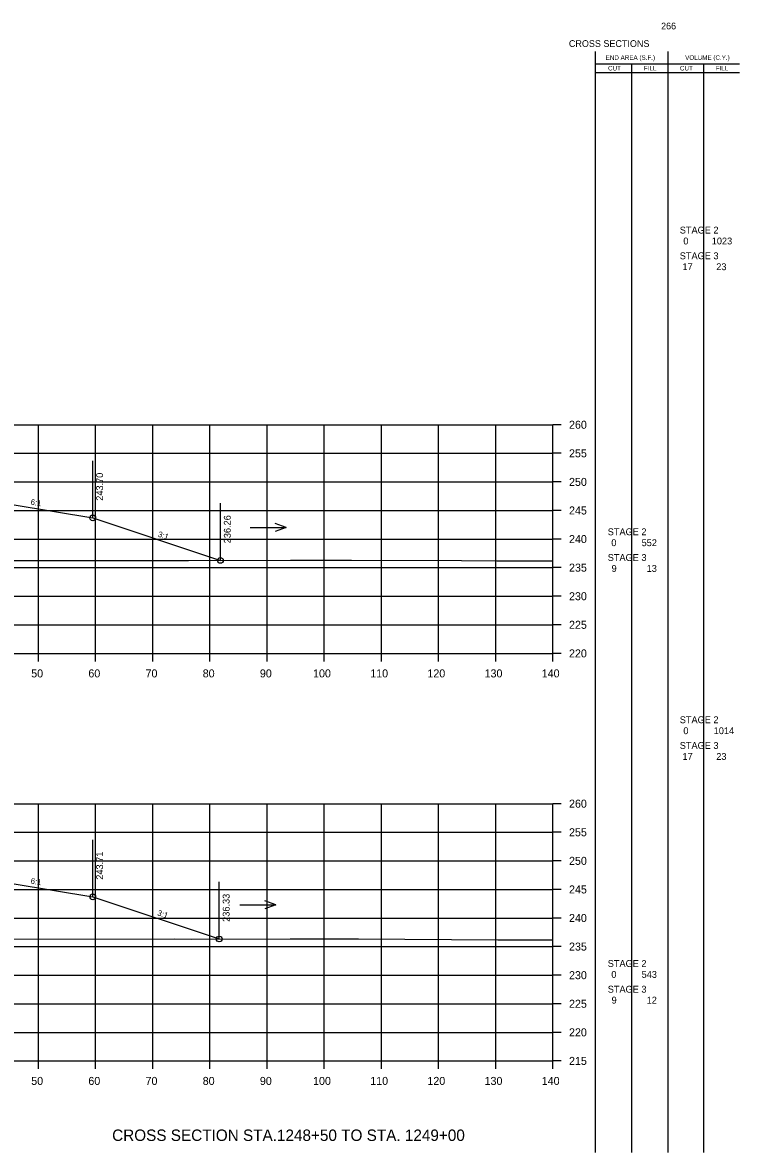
# Model space of a CAD drawing. Extents: x 1342547 to 1344156, y -1532351 to -1517216.
# Drawn here: x 1342750.1 to 1342875.5, y -1527653.7 to -1527456.1 of the extents above; entities that cross this region are included whole.
import ezdxf

# ---------------------------------------------------------------- set-up
doc = ezdxf.new("R2010")
doc.units = 0
for name, color, linetype in [('Level 2', 7, 'Continuous'), ('R_Axis', 7, 'Continuous'), ('R_Axis Annot', 7, 'Continuous'), ('R_Border Notes', 7, 'Continuous'), ('R_Draft', 7, 'Continuous'), ('R_Exist Surface', 7, 'Continuous'), ('R_Fin Surface', 7, 'Continuous'), ('R_Grid', 7, 'Continuous'), ('R_No Plot', 7, 'Continuous'), ('R_Water', 7, 'Continuous'), ('R_Xsect Elev', 7, 'Continuous'), ('R_Xsect Slope', 7, 'Continuous')]:
    doc.layers.add(name, color=color, linetype=linetype)

msp = doc.modelspace()

# ---------------------------------------------------------------- linework, layer by layer
at = {"layer": 'Level 2'}
for p, q in [((1342850.33, -1527653.71), (1342850.32, -1527461.11)), ((1342862.99, -1527653.71), (1342862.99, -1527461.11)), ((1342850.32, -1527463.27), (1342863.59, -1527463.27)), ((1342856.66, -1527653.71), (1342856.66, -1527463.27)), ((1342863.59, -1527463.27), (1342875.48, -1527463.27)), ((1342869.23, -1527653.71), (1342869.23, -1527463.27)), ((1342850.32, -1527464.83), (1342863.59, -1527464.83)), ((1342863.59, -1527464.83), (1342875.48, -1527464.83))]:
    msp.add_line(p, q, dxfattribs=at)
at = {"layer": 'R_Axis'}
for p, q in [((1342842.87, -1527566.42), (1342842.87, -1527526.42)), ((1342844.27, -1527526.42), (1342842.87, -1527526.42)), ((1342844.27, -1527531.42), (1342842.87, -1527531.42)), ((1342844.27, -1527536.42), (1342842.87, -1527536.42)), ((1342844.27, -1527541.42), (1342842.87, -1527541.42)), ((1342844.27, -1527546.42), (1342842.87, -1527546.42)), ((1342844.27, -1527551.42), (1342842.87, -1527551.42)), ((1342844.27, -1527556.42), (1342842.87, -1527556.42)), ((1342844.27, -1527561.42), (1342842.87, -1527561.42)), ((1342562.87, -1527566.42), (1342842.87, -1527566.42)), ((1342752.87, -1527567.82), (1342752.87, -1527566.42)), ((1342762.87, -1527567.82), (1342762.87, -1527566.42)), ((1342772.87, -1527567.82), (1342772.87, -1527566.42)), ((1342782.87, -1527567.82), (1342782.87, -1527566.42)), ((1342792.87, -1527567.82), (1342792.87, -1527566.42)), ((1342802.87, -1527567.82), (1342802.87, -1527566.42)), ((1342812.87, -1527567.82), (1342812.87, -1527566.42)), ((1342822.87, -1527567.82), (1342822.87, -1527566.42)), ((1342832.87, -1527567.82), (1342832.87, -1527566.42)), ((1342842.87, -1527567.82), (1342842.87, -1527566.42)), ((1342844.27, -1527566.42), (1342842.87, -1527566.42)), ((1342842.87, -1527637.71), (1342842.87, -1527592.71)), ((1342844.27, -1527592.71), (1342842.87, -1527592.71)), ((1342844.27, -1527597.71), (1342842.87, -1527597.71)), ((1342844.27, -1527602.71), (1342842.87, -1527602.71)), ((1342844.27, -1527607.71), (1342842.87, -1527607.71)), ((1342844.27, -1527612.71), (1342842.87, -1527612.71)), ((1342844.27, -1527617.71), (1342842.87, -1527617.71)), ((1342844.27, -1527622.71), (1342842.87, -1527622.71)), ((1342844.27, -1527627.71), (1342842.87, -1527627.71)), ((1342844.27, -1527632.71), (1342842.87, -1527632.71)), ((1342562.87, -1527637.71), (1342842.87, -1527637.71)), ((1342752.87, -1527639.11), (1342752.87, -1527637.71)), ((1342762.87, -1527639.11), (1342762.87, -1527637.71)), ((1342772.87, -1527639.11), (1342772.87, -1527637.71)), ((1342782.87, -1527639.11), (1342782.87, -1527637.71)), ((1342792.87, -1527639.11), (1342792.87, -1527637.71)), ((1342802.87, -1527639.11), (1342802.87, -1527637.71)), ((1342812.87, -1527639.11), (1342812.87, -1527637.71)), ((1342822.87, -1527639.11), (1342822.87, -1527637.71)), ((1342832.87, -1527639.11), (1342832.87, -1527637.71)), ((1342842.87, -1527639.11), (1342842.87, -1527637.71)), ((1342844.27, -1527637.71), (1342842.87, -1527637.71))]:
    msp.add_line(p, q, dxfattribs=at)
at = {"layer": 'R_Exist Surface'}
for points in [[(1342747.23, -1527550.16), (1342761.1, -1527550.15), (1342779.11, -1527550.19), (1342796.93, -1527550.12), (1342807.63, -1527550.1), (1342826.89, -1527550.16), (1342833.04, -1527550.2), (1342841.28, -1527550.24), (1342842.87, -1527550.25)], [(1342748.04, -1527616.39), (1342776.72, -1527616.38), (1342779.65, -1527616.39), (1342796.91, -1527616.37), (1342807.63, -1527616.35), (1342808.84, -1527616.36), (1342833.2, -1527616.5), (1342842.87, -1527616.55)]]:
    msp.add_lwpolyline(points, dxfattribs=at)
at = {"layer": 'R_Fin Surface'}
for points in [[(1342638.73, -1527544.26), (1342643.37, -1527542.72), (1342657.09, -1527540.43), (1342665.37, -1527539.05), (1342671.37, -1527538.81), (1342673.37, -1527538.77), (1342702.87, -1527538.18), (1342732.37, -1527538.77), (1342734.37, -1527538.81), (1342740.37, -1527539.05), (1342748.64, -1527540.43), (1342762.37, -1527542.72), (1342784.7, -1527550.16)], [(1342639.21, -1527610.39), (1342643.37, -1527609.01), (1342657.09, -1527606.72), (1342665.37, -1527605.34), (1342671.37, -1527605.1), (1342673.37, -1527605.06), (1342702.87, -1527604.47), (1342732.37, -1527605.06), (1342734.37, -1527605.1), (1342740.37, -1527605.34), (1342748.64, -1527606.72), (1342762.37, -1527609.01), (1342784.5, -1527616.38)]]:
    msp.add_lwpolyline(points, dxfattribs=at)
at = {"layer": 'R_Grid'}
for p, q in [((1342562.87, -1527526.42), (1342842.87, -1527526.42)), ((1342752.87, -1527566.42), (1342752.87, -1527526.42)), ((1342762.87, -1527566.42), (1342762.87, -1527526.42)), ((1342772.87, -1527566.42), (1342772.87, -1527526.42)), ((1342782.87, -1527566.42), (1342782.87, -1527526.42)), ((1342792.87, -1527566.42), (1342792.87, -1527526.42)), ((1342802.87, -1527566.42), (1342802.87, -1527526.42)), ((1342812.87, -1527566.42), (1342812.87, -1527526.42)), ((1342822.87, -1527566.42), (1342822.87, -1527526.42)), ((1342832.87, -1527566.42), (1342832.87, -1527526.42)), ((1342842.87, -1527566.42), (1342842.87, -1527526.42)), ((1342562.87, -1527531.42), (1342842.87, -1527531.42)), ((1342562.87, -1527536.42), (1342842.87, -1527536.42)), ((1342562.87, -1527541.42), (1342842.87, -1527541.42)), ((1342562.87, -1527546.42), (1342842.87, -1527546.42)), ((1342562.87, -1527551.42), (1342842.87, -1527551.42)), ((1342562.87, -1527556.42), (1342842.87, -1527556.42)), ((1342562.87, -1527561.42), (1342842.87, -1527561.42)), ((1342562.87, -1527566.42), (1342842.87, -1527566.42)), ((1342562.87, -1527592.71), (1342842.87, -1527592.71)), ((1342752.87, -1527637.71), (1342752.87, -1527592.71)), ((1342762.87, -1527637.71), (1342762.87, -1527592.71)), ((1342772.87, -1527637.71), (1342772.87, -1527592.71)), ((1342782.87, -1527637.71), (1342782.87, -1527592.71)), ((1342792.87, -1527637.71), (1342792.87, -1527592.71)), ((1342802.87, -1527637.71), (1342802.87, -1527592.71)), ((1342812.87, -1527637.71), (1342812.87, -1527592.71)), ((1342822.87, -1527637.71), (1342822.87, -1527592.71)), ((1342832.87, -1527637.71), (1342832.87, -1527592.71)), ((1342842.87, -1527637.71), (1342842.87, -1527592.71)), ((1342562.87, -1527597.71), (1342842.87, -1527597.71)), ((1342562.87, -1527602.71), (1342842.87, -1527602.71)), ((1342562.87, -1527607.71), (1342842.87, -1527607.71)), ((1342562.87, -1527612.71), (1342842.87, -1527612.71)), ((1342562.87, -1527617.71), (1342842.87, -1527617.71)), ((1342562.87, -1527622.71), (1342842.87, -1527622.71)), ((1342562.87, -1527627.71), (1342842.87, -1527627.71)), ((1342562.87, -1527632.71), (1342842.87, -1527632.71)), ((1342562.87, -1527637.71), (1342842.87, -1527637.71))]:
    msp.add_line(p, q, dxfattribs=at)
at = {"layer": 'R_No Plot'}
for centre in [(1342762.37, -1527542.72), (1342784.7, -1527550.16), (1342762.37, -1527609.01), (1342784.5, -1527616.38)]:
    msp.add_circle(centre, 0.5, dxfattribs=at)
at = {"layer": 'R_Water'}
for p, q in [((1342789.91, -1527544.38), (1342796.19, -1527544.38)), ((1342796.19, -1527544.38), (1342794.27, -1527543.68)), ((1342796.19, -1527544.38), (1342794.27, -1527545.08)), ((1342788.11, -1527610.42), (1342794.39, -1527610.42)), ((1342794.39, -1527610.42), (1342792.47, -1527609.72)), ((1342794.39, -1527610.42), (1342792.47, -1527611.12))]:
    msp.add_line(p, q, dxfattribs=at)
at = {"layer": 'R_Xsect Elev'}
for p, q in [((1342762.37, -1527542.72), (1342762.37, -1527532.72)), ((1342784.7, -1527550.16), (1342784.7, -1527540.16)), ((1342762.37, -1527609.01), (1342762.37, -1527599.01)), ((1342784.5, -1527616.38), (1342784.5, -1527606.38))]:
    msp.add_line(p, q, dxfattribs=at)

# ---------------------------------------------------------------- texts
at = {"layer": 'Level 2'}
for s, height, p in [('END AREA (S.F.)', 0.7937, (1342852.08, -1527462.59)), ('VOLUME (C.Y.)', 0.7937, (1342865.99, -1527462.59)), ('CUT', 0.794, (1342852.5, -1527464.45)), ('FILL', 0.794, (1342858.76, -1527464.45)), ('CUT', 0.794, (1342865.07, -1527464.45)), ('FILL', 0.794, (1342871.33, -1527464.45)), (' STAGE 2 ', 1.2, (1342864.6, -1527492.97)), ('0', 1.2, (1342865.67, -1527494.88)), ('1023', 1.2, (1342870.64, -1527494.88)), (' STAGE 3 ', 1.2, (1342864.6, -1527497.47)), ('17', 1.2, (1342865.52, -1527499.38)), ('23', 1.2, (1342871.43, -1527499.38)), (' STAGE 2 ', 1.2, (1342852, -1527545.75)), ('0', 1.2, (1342853.07, -1527547.66)), ('552', 1.2, (1342858.37, -1527547.66)), (' STAGE 3 ', 1.2, (1342852, -1527550.25)), ('9', 1.2, (1342853.12, -1527552.16)), ('13', 1.2, (1342859.25, -1527552.16)), (' STAGE 2 ', 1.2, (1342864.6, -1527578.63)), ('0', 1.2, (1342865.67, -1527580.55)), ('1014', 1.2, (1342870.98, -1527580.55)), (' STAGE 3 ', 1.2, (1342864.6, -1527583.13)), ('17', 1.2, (1342865.52, -1527585.05)), ('23', 1.2, (1342871.43, -1527585.05)), (' STAGE 2 ', 1.2, (1342852, -1527621.27)), ('0', 1.2, (1342853.07, -1527623.18)), ('543', 1.2, (1342858.37, -1527623.18)), (' STAGE 3 ', 1.2, (1342852, -1527625.77)), ('9', 1.2, (1342853.12, -1527627.68)), ('12', 1.2, (1342859.25, -1527627.68))]:
    msp.add_text(s, height=height, dxfattribs=at).set_placement(p)
at = {"layer": 'R_Axis Annot'}
for s, p in [('260', (1342845.67, -1527527.12)), ('255', (1342845.67, -1527532.12)), ('250', (1342845.67, -1527537.12)), ('245', (1342845.67, -1527542.12)), ('240', (1342845.67, -1527547.12)), ('235', (1342845.67, -1527552.12)), ('230', (1342845.67, -1527557.12)), ('225', (1342845.67, -1527562.12)), ('220', (1342845.67, -1527567.12)), ('50', (1342751.6, -1527570.62)), ('60', (1342761.6, -1527570.62)), ('70', (1342771.6, -1527570.62)), ('80', (1342781.6, -1527570.62)), ('90', (1342791.6, -1527570.62)), ('100', (1342800.9, -1527570.62)), ('110', (1342810.9, -1527570.62)), ('120', (1342820.9, -1527570.62)), ('130', (1342830.9, -1527570.62)), ('140', (1342840.9, -1527570.62)), ('260', (1342845.67, -1527593.41)), ('255', (1342845.67, -1527598.41)), ('250', (1342845.67, -1527603.41)), ('245', (1342845.67, -1527608.41)), ('240', (1342845.67, -1527613.41)), ('235', (1342845.67, -1527618.41)), ('230', (1342845.67, -1527623.41)), ('225', (1342845.67, -1527628.41)), ('220', (1342845.67, -1527633.41)), ('215', (1342845.67, -1527638.41)), ('50', (1342751.6, -1527641.91)), ('60', (1342761.6, -1527641.91)), ('70', (1342771.6, -1527641.91)), ('80', (1342781.6, -1527641.91)), ('90', (1342791.6, -1527641.91)), ('100', (1342800.9, -1527641.91)), ('110', (1342810.9, -1527641.91)), ('120', (1342820.9, -1527641.91)), ('130', (1342830.9, -1527641.91)), ('140', (1342840.9, -1527641.91))]:
    msp.add_text(s, height=1.4, dxfattribs=at).set_placement(p)
at = {"layer": 'R_Border Notes'}
for s, height, p in [('266', 1.178, (1342861.77, -1527457.27)), ('CROSS SECTIONS', 1.1775, (1342845.65, -1527460.33))]:
    msp.add_text(s, height=height, dxfattribs=at).set_placement(p)
at = {"layer": 'R_Draft'}
msp.add_text('CROSS SECTION STA.1248+50 TO STA. 1249+00', height=2, dxfattribs=at).set_placement((1342765.76, -1527651.71))
at = {"layer": 'R_Xsect Elev'}
for s, p in [('243.70', (1342764.17, -1527539.72)), ('236.26', (1342786.5, -1527547.16)), ('243.71', (1342764.17, -1527606.01)), ('236.33', (1342786.3, -1527613.38))]:
    msp.add_text(s, height=1.2, rotation=90, dxfattribs=at).set_placement(p)
at = {"layer": 'R_Xsect Slope'}
for s, rotation, p in [('6:1', 350.5377, (1342751.45, -1527540.39)), ('3:1', 341.5651, (1342773.69, -1527545.97)), ('6:1', 350.5377, (1342751.45, -1527606.68)), ('3:1', 341.5651, (1342773.59, -1527612.22))]:
    msp.add_text(s, height=1, rotation=rotation, dxfattribs=at).set_placement(p)

doc.saveas('drawing.dxf')
